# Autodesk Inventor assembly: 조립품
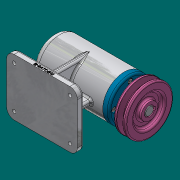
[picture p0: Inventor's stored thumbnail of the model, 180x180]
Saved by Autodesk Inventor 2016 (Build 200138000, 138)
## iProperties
Created: 2020-10
Part Number: 조립품
Material: 일반
Document SubType Name: Assembly
Designer: 605-15
Author: 605-15
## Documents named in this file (12)
- C:\Users\605-15\Desktop\701004V1002\조립품.iam
- C:\Users\605-15\Desktop\701004V1002\본체.ipt
- C:\Users\605-15\Desktop\701004V1002\베어링 6004.ipt
- C:\Users\605-15\Desktop\701004V1002\어댑터슬리브.ipt
- C:\Users\605-15\Desktop\701004V1002\베어링 51202.ipt
- C:\Users\605-15\Desktop\701004V1002\커버.ipt
- C:\Users\605-15\Desktop\701004V1002\오일 실.ipt
- C:\Users\605-15\Desktop\701004V1002\축.ipt
- C:\Users\605-15\Desktop\701004V1002\Ű 5 x 5 x 16.ipt
- C:\Users\605-15\Desktop\701004V1002\V벨트풀리.ipt
- C:\Users\605-15\Desktop\701004V1002\멈춤나사 M3.ipt
- C:\Users\605-15\Desktop\701004V1002\볼트 M4.ipt
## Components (2 placed, 2 different names)
1. Ű 5 x 5 x 16:1
2. V벨트풀리:1
